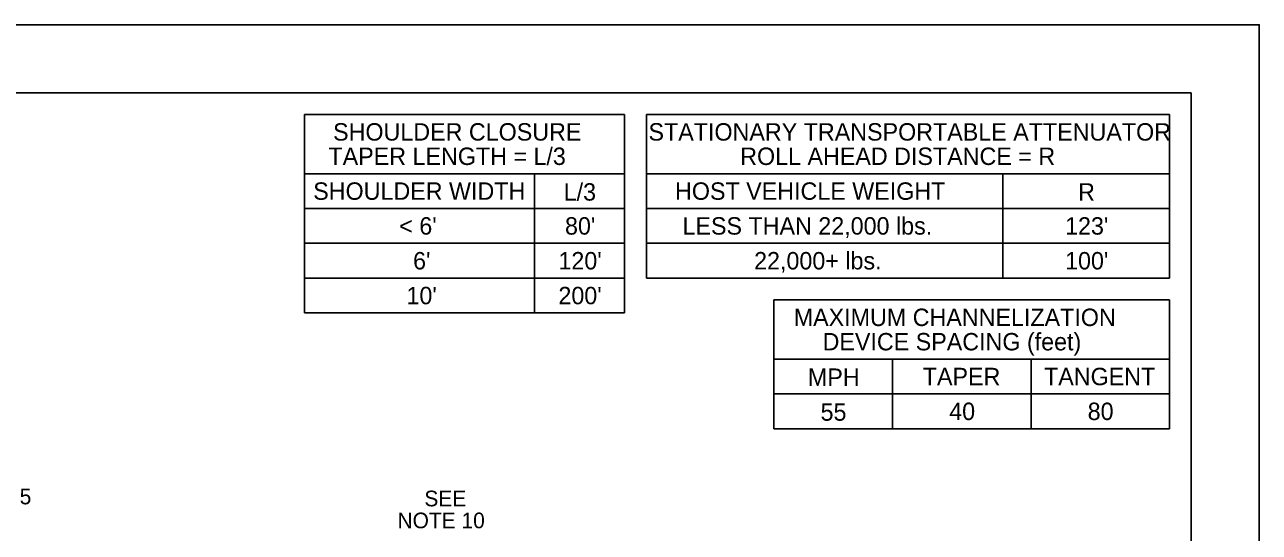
# Model space of a CAD drawing. Extents: x 99999 to 100116, y 99995 to 100013.
# Drawn here: x 100010.39 to 100016.06, y 100008.36 to 100010.69 of the extents above; entities that cross this region are included whole.
import ezdxf

# ---------------------------------------------------------------- set-up
doc = ezdxf.new("R2010")
doc.units = 0
for name, color, linetype in [('SH_GI_PlotLimits', 7, 'Continuous'), ('SH_GI_SheetBorder', 7, 'Continuous'), ('SH_TI_Tables', 7, 'Continuous'), ('TR_SN_ConstructionSigns', 7, 'Continuous')]:
    doc.layers.add(name, color=color, linetype=linetype)

msp = doc.modelspace()

# ---------------------------------------------------------------- linework, layer by layer
at = {"layer": 'SH_GI_PlotLimits'}
msp.add_lwpolyline([(99999.0625, 99999.6875), (100016.0625, 99999.6875), (100016.0625, 100010.6875), (99999.0625, 100010.6875)], close=True, dxfattribs=at)
at = {"layer": 'SH_GI_SheetBorder'}
for p, q in [((100000, 100010.375), (100015.75, 100010.375)), ((100015.75, 100010.375), (100015.75, 100000))]:
    msp.add_line(p, q, dxfattribs=at)
at = {"layer": 'SH_TI_Tables'}
for p, q in [((100011.6742, 100010.275), (100013.1454, 100010.275)), ((100011.6742, 100009.363), (100011.6742, 100010.275)), ((100013.1454, 100009.363), (100013.1454, 100010.275)), ((100013.2454, 100010.275), (100015.65, 100010.275)), ((100013.2454, 100009.523), (100013.2454, 100010.275)), ((100015.65, 100009.523), (100015.65, 100010.275)), ((100011.6742, 100010.003), (100013.1454, 100010.003)), ((100012.7319, 100010.003), (100012.7319, 100009.363)), ((100013.2454, 100010.003), (100014.8844, 100010.003)), ((100014.8844, 100010.003), (100014.8844, 100009.843)), ((100014.8844, 100010.003), (100015.65, 100010.003)), ((100011.6742, 100009.843), (100012.7319, 100009.843)), ((100012.7319, 100009.843), (100013.1454, 100009.843)), ((100013.2454, 100009.843), (100014.8844, 100009.843)), ((100014.8844, 100009.843), (100015.65, 100009.843)), ((100014.8844, 100009.843), (100014.8844, 100009.683)), ((100011.6742, 100009.683), (100012.7319, 100009.683)), ((100012.7319, 100009.683), (100013.1454, 100009.683)), ((100013.2454, 100009.683), (100014.8844, 100009.683)), ((100014.8844, 100009.683), (100015.65, 100009.683)), ((100014.8844, 100009.683), (100014.8844, 100009.523)), ((100011.6742, 100009.523), (100012.7319, 100009.523)), ((100012.7319, 100009.523), (100013.1454, 100009.523)), ((100013.2454, 100009.523), (100015.65, 100009.523)), ((100013.8318, 100009.423), (100015.65, 100009.423)), ((100013.8318, 100008.831), (100013.8318, 100009.423)), ((100015.65, 100008.831), (100015.65, 100009.423)), ((100011.6742, 100009.363), (100012.7319, 100009.363)), ((100012.7319, 100009.363), (100013.1454, 100009.363)), ((100013.8318, 100009.151), (100015.65, 100009.151)), ((100014.3773, 100008.831), (100014.3773, 100009.151)), ((100015.0136, 100008.831), (100015.0136, 100009.151)), ((100013.8318, 100008.991), (100014.3773, 100008.991)), ((100014.3773, 100008.991), (100015.0136, 100008.991)), ((100015.0136, 100008.991), (100015.65, 100008.991)), ((100013.8318, 100008.831), (100015.65, 100008.831))]:
    msp.add_line(p, q, dxfattribs=at)

# ---------------------------------------------------------------- texts
for s, p in [('SHOULDER CLOSURE', (100011.8055, 100010.155)), ('STATIONARY TRANSPORTABLE ATTENUATOR ', (100013.2552, 100010.155)), ('TAPER LENGTH = L/3', (100011.7842, 100010.043)), ('ROLL AHEAD DISTANCE = R', (100013.6767, 100010.043)), ('SHOULDER WIDTH', (100011.7142, 100009.883)), ('L/3', (100012.8654, 100009.8792)), ('HOST VEHICLE WEIGHT', (100013.3773, 100009.883)), ('R', (100015.2296, 100009.8792)), ("< 6'", (100012.1096, 100009.723)), ("80'", (100012.8714, 100009.723)), ('LESS THAN 22,000 lbs.', (100013.4114, 100009.723)), ("123'", (100015.1698, 100009.723)), ("6'", (100012.1731, 100009.563)), ("120'", (100012.8412, 100009.563)), ('22,000+ lbs.', (100013.7405, 100009.563)), ("100'", (100015.1698, 100009.563)), ("10'", (100012.1428, 100009.403)), ("200'", (100012.8412, 100009.403)), ('MAXIMUM CHANNELIZATION', (100013.9227, 100009.303)), ('DEVICE SPACING (feet)', (100014.0553, 100009.191)), ('MPH', (100013.9878, 100009.0279)), ('TAPER', (100014.5157, 100009.031)), ('TANGENT', (100015.0731, 100009.031)), ('40', (100014.6373, 100008.871)), ('80', (100015.2737, 100008.871))]:
    msp.add_text(s, height=0.08, rotation=360, dxfattribs=at).set_placement(p)
msp.add_text('55', height=0.08, dxfattribs=at).set_placement((100014.0461, 100008.8679))
at = {"layer": 'TR_SN_ConstructionSigns'}
for s, p in [('SEE NOTE 5', (100009.8515, 100008.4838)), ('SEE', (100012.2251, 100008.4745)), ('NOTE 10', (100012.1015, 100008.3737))]:
    msp.add_text(s, height=0.072, rotation=360, dxfattribs=at).set_placement(p)

doc.saveas('drawing.dxf')
